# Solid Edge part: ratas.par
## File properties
Author: argo
Template: Iso Part.par
Last saved by: Argu
Revision: 10
Application: Solid Edge
Accuracy: 0,990
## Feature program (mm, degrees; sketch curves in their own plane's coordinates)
sketch for "unnamed Protrusion 1" plane through (0, 0, 0) normal (1, 0, 0) x-axis (0, 1, 0)
  circle centre (0, 0) radius 3
extrude "unnamed Protrusion 1" add finite 9 along +normal
sketch for "unnamed RevolvedProtrusion 1" plane through (0, 0, 0) normal (0, -1, 0) x-axis (1, 0, 0)
  circle centre (9, 9) radius 3
revolve "unnamed RevolvedProtrusion 1" add finite 360 deg
sketch for "unnamed RevolvedCutout 1" plane through (0, 0, 0) normal (0, -1, 0) x-axis (1, 0, 0)
  line (9.1999, 11.9933) -> (9.1999, 11.7933)
  line (9.1999, 11.7933) -> (8.7999, 11.7933)
  line (8.7999, 11.7933) -> (8.7999, 11.9933)
  line (8.7999, 11.9933) -> (8.7999, 12.1177)
  line (9.1986, 12.1177) -> (8.7999, 12.1177)
  line (9.1986, 11.9934) -> (9.1986, 12.1177)
  arc centre (9, 9) radius 3 from (9.1999, 11.9933) to (9.1986, 11.9934) ccw
revolve "unnamed RevolvedCutout 1" cut finite 360 deg
sketch for "unnamed RevolvedCutout 2" #1 plane through (0, 0, 0) normal (0, -1, 0) x-axis (1, 0, 0)
  circle centre (11.6336, 10.4368) radius 0.2
sketch for "unnamed RevolvedCutout 2" #2 plane through (0, 0, 0) normal (0, -1, 0) x-axis (1, 0, 0)
  circle centre (11.015, 11.2225) radius 0.2
sketch for "unnamed RevolvedCutout 2" #3 plane through (0, 0, 0) normal (0, -1, 0) x-axis (1, 0, 0)
  circle centre (10.1726, 11.7613) radius 0.2
revolve "unnamed RevolvedCutout 2" cut finite 360 deg
mirror "unnamed Mirror 1" of "unnamed RevolvedCutout 2" about plane through (8.9993, 0, 0) normal (1, 0, 0)
revolve "unnamed RevolvedCutout 3" cut finite 360 deg
sketch for "unnamed RevolvedProtrusion 2" plane through (0, 0, 0) normal (0, -1, 0) x-axis (1, 0, 0)
  line (6.0614, 8.0131) -> (5.6641, 7.6456)
  arc centre (8.9998, 8.9995) radius 3.6 from (7.2846, 5.8344) to (5.6641, 7.6456) cw
  arc centre (5.7234, 2.9536) radius 3.2766 from (9, 2.9536) to (7.2846, 5.8344) ccw
  line (9, 2.9536) -> (9, 0)
  line (9, 0) -> (9.6379, 0)
  line (9.6379, 0) -> (9.6379, 2.9536)
  arc centre (15.5166, 2.014) radius 5.9533 from (11.4556, 6.3672) to (9.6379, 2.9536) ccw
  line (11.9383, 8.0135) -> (12.3355, 7.6456)
revolve "unnamed RevolvedProtrusion 2" add finite 360 deg
chamfer "unnamed Chamfer 1"
chamfer "veljeteineserv" setback 1
fillet "veljekujundus" radius 0.5
body pattern "unnamed BodyPattern 1"
pattern "unnamed Pattern 1"
sketch for "ExtrudedProtrusion_3" plane through (0, 0, 0) normal (1, 0, 0) x-axis (0, 1, 0)
  line (-2.9146, 2.7395) -> (-13.7302, 5.8227)
  line (-13.7302, 22.9132) -> (-13.7302, 5.8227)
  line (-21.939, 22.9132) -> (-13.7302, 22.9132)
  line (-21.939, 2.8622) -> (-21.939, 22.9132)
  line (-3.1206, -2.5024) -> (-21.939, 2.8622)
  line (27.3138, 0) -> (4, 0)
  line (27.3138, 1.9707) -> (27.3138, 0)
  line (13.3184, 1.9707) -> (27.3138, 1.9707)
  line (3.4809, 1.9707) -> (13.3184, 1.9707)
  arc centre (0, 0) radius 4 from (-2.9146, 2.7395) to (3.4809, 1.9707) cw
extrude "ExtrudedProtrusion_3" add finite 5 symmetric
sketch for "unnamed Protrusion 2" plane through (0, 15.3973, 1.9707) normal (0, 0, 1) x-axis (1, 0, 0)
  circle centre (0, 5.7835) radius 7.0893
extrude "unnamed Protrusion 2" add to key point along -normal
sketch for "ExtrudedProtrusion_5" plane through (0, -17.8346, 22.9132) normal (0, 0, 1) x-axis (0, -1, 0)
  line (-51.0734, -14) -> (-51.0734, 14)
  line (-51.0734, 14) -> (3.9266, 14)
  line (3.9266, 0) -> (3.9266, 14)
  line (3.9266, 0) -> (3.9266, -14)
  line (3.9266, -14) -> (-51.0734, -14)
extrude "ExtrudedProtrusion_5" add finite 2 along +normal
logasc func "Lip_Groove_1"  LipOrGrooveWidth = 1 mm; LipOrGrooveHeight = 2 mm
fillet "Round_2" radius 1
sketch for "unnamed RevolvedCutout 4" plane through (0, 0, 0) normal (1, 0, 0) x-axis (0, 1, 0)
  line (16.5612, 2.9707) -> (21.4086, 2.9707)
  line (21.4086, 1.9707) -> (21.4086, 2.9707)
  line (21.4086, 1.9707) -> (21.4086, 0.9544)
  line (16.5612, 0.9707) -> (21.4086, 0.9544)
revolve "unnamed RevolvedCutout 4" cut full turn 360 deg
fillet "Round_3" radius 2
fillet "Round_4" radius 1
fillet "Round_6" radius 5
fillet "Round_7" radius 1
fillet "Round_8" radius 5
helix protrusion "amordivedru"  Pitch = 4 mm
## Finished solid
Body 1: solid body, 120 faces, 196 edges, 78 vertices, 3 separate solids.
  Faces by surface: torus 49, plane 25, cylinder 24, blend 14, cone 5, sphere 2, spline 1
  Edges by curve: circle 105, line 58, intersection 29, ellipse 4
Bounding box of the edges (mm; curved faces can reach further): 28.000 x 55.178 x 36.907, from (-14, -21.939, -11.9933) to (14, 33.2388, 24.9132).
Cylindrical faces by radius (mm): R1 x4, R2 x9, R3 x2, R4 x2, R5 x5, R11.7933 x2
Conical faces (half-angle, radius in mm at the cone's reference point): 89.808 deg R0 x1, 89.8303 deg R8.4756 x2, 89.9002 deg R6.3482 x2
Toroidal faces (ring radius, tube radius in mm): R2.014 r5.9533 x2, R2.9536 r3.2766 x2, R3 r1 x4, R4.3572 r1 x1, R4.8474 r1 x1, R6 r1 x2, R6.0893 r1 x1, R6.0897 r1 x1, R6.5687 r0.5 x2, R6.5781 r0.5 x2, R6.5794 r1 x1, R8.9995 r3.0995 x2, R8.9995 r3.6 x2, R9 r3 x14, R10.4368 r0.2 x4, R11.2225 r0.2 x4, R11.7613 r0.2 x4
Spherical faces by radius (mm): R2 x2
Planar faces by outward normal: +x 6, +y 2, +z 3, -x 7, -y 2, -z 3, oblique 2
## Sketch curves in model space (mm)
circle centre (0, 16.7857, 1.4707) radius 0.5
line (0, 21.4086, 0.9544) -> (0, 21.4086, 22.9527)
line (-45.3688, 19.1088, 0) -> (-45.3688, 32.0043, 0)
line (-45.3688, 32.0043, 0) -> (-33.8801, 32.0043, 0)
line (-33.8801, 32.0043, 0) -> (-33.8801, 19.1088, 0)
line (-33.8801, 19.1088, 0) -> (-45.3688, 19.1088, 0)
line (0, 21.4086, 3.981) -> (0, 21.4086, 24.9132)
line (0, 16.5612, 2.9707) -> (0, 21.4086, 2.9707)
arc centre (0, 16.5612, 1.9707) radius 1 from (0, 16.5612, 0.9707) through (0, 15.5616, 2.0003) to (0, 16.5612, 2.9707)
line (0, 16.5612, 0.9707) -> (0, 21.4086, 0.9544)
line (0, 21.4086, 1.9707) -> (0, 21.4086, 0.9544)
line (0, 21.4086, 1.9707) -> (0, 21.4086, 2.9707)
line (0, 21.4086, 1.9707) -> (0, 21.4086, 24.9132)
line (-14, -21.7612, 22.9132) -> (-14, 33.2388, 22.9132)
line (-14, 33.2388, 22.9132) -> (14, 33.2388, 22.9132)
line (14, 33.2388, 22.9132) -> (14, -21.7612, 22.9132)
line (0, -21.7612, 22.9132) -> (14, -21.7612, 22.9132)
line (0, -21.7612, 22.9132) -> (-14, -21.7612, 22.9132)
circle centre (0, 21.1808, 1.9707) radius 7.0893
line (6.0614, 0, 8.0131) -> (5.6641, 0, 7.6456)
arc centre (8.9998, 0, 8.9995) radius 3.6 from (7.2846, 0, 5.8344) through (6.3169, 0, 6.5991) to (5.6641, 0, 7.6456)
arc centre (5.7234, 0, 2.9536) radius 3.2766 from (9, 0, 2.9536) through (8.5387, 0, 4.6301) to (7.2846, 0, 5.8344)
line (9, 0, 2.9536) -> (9, 0, 0)
line (9, 0, 0) -> (9.6379, 0, 0)
line (9.6379, 0, 0) -> (9.6379, 0, 2.9536)
arc centre (15.5166, 0, 2.014) radius 5.9533 from (11.4556, 0, 6.3672) through (10.2618, 0, 4.8121) to (9.6379, 0, 2.9536)
arc centre (8.9998, 0, 8.9995) radius 3.6 from (12.3355, 0, 7.6456) through (11.9652, 0, 6.9584) to (11.4556, 0, 6.3672)
line (11.9383, 0, 8.0135) -> (12.3355, 0, 7.6456)
arc centre (8.9998, 0, 8.9995) radius 3.0995 from (11.9383, 0, 8.0135) through (9, 0, 5.9) to (6.0614, 0, 8.0131)
line (9, 0, 5.9073) -> (9, 0, 5.9)
line (9.6379, 0, 5.9073) -> (9, 0, 5.9073)
line (0, -13.7302, 22.9132) -> (0, -13.7302, 5.8227)
line (0, -21.939, 22.9132) -> (0, -13.7302, 22.9132)
line (0, -21.939, 2.8622) -> (0, -21.939, 22.9132)
line (0, -3.1206, -2.5024) -> (0, -21.939, 2.8622)
arc centre (0, 0, 0) radius 4 from (0, 4, 0) through (0, 1.3262, -3.7738) to (0, -3.1206, -2.5024)
line (0, 27.3138, 0) -> (0, 4, 0)
line (0, 27.3138, 1.9707) -> (0, 27.3138, 0)
line (0, 13.3184, 1.9707) -> (0, 27.3138, 1.9707)
line (0, 3.4809, 1.9707) -> (0, 13.3184, 1.9707)
arc centre (0, 0, 0) radius 4 from (0, -2.9146, 2.7395) through (0, 0.4774, 3.9714) to (0, 3.4809, 1.9707)
line (0, -2.9146, 2.7395) -> (0, -13.7302, 5.8227)
circle centre (11.6336, 0, 10.4368) radius 0.2
circle centre (11.015, 0, 11.2225) radius 0.2
circle centre (10.1726, 0, 11.7613) radius 0.2
line (8.9993, 0, 12.1177) -> (8.9993, 0, 12.9208)
line (0, 0, 0) -> (27.9552, 0, 0)
line (9.1999, 0, 11.9933) -> (9.1999, 0, 11.7933)
line (9.1999, 0, 11.7933) -> (8.7999, 0, 11.7933)
line (8.7999, 0, 11.7933) -> (8.7999, 0, 11.9933)
line (8.7999, 0, 11.9933) -> (8.7999, 0, 12.1177)
line (9.1986, 0, 12.1177) -> (8.7999, 0, 12.1177)
line (9.1986, 0, 11.9934) -> (9.1986, 0, 12.1177)
arc centre (9, 0, 9) radius 3 from (9.1999, 0, 11.9933) through (9.1993, 0, 11.9934) to (9.1986, 0, 11.9934)
line (11.015, 0, 11.2225) -> (11.6336, 0, 10.4368)
line (10.1726, 0, 11.7613) -> (11.015, 0, 11.2225)
line (9.1999, 0, 11.9933) -> (10.1726, 0, 11.7613)
circle centre (9, 0, 9) radius 3
line (14.0515, 0, 0) -> (-4.1642, 0, 0)
circle centre (0, 0, 0) radius 3
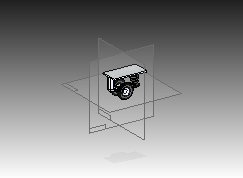
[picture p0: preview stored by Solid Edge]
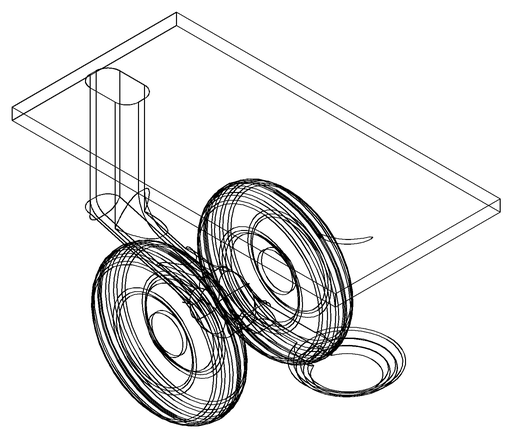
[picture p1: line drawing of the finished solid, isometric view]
